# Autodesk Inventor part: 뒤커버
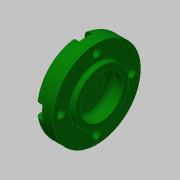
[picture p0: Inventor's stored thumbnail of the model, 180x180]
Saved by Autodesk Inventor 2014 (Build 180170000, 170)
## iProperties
Created: 2015-11
Part Number: 뒤커버
Material: 알루미늄 6061
Document SubType Name: Modeling
Designer: mduedu
Density: 1 g/cm^3
Appearance: 진녹색
Author: mduedu
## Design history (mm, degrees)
sketch "스케치1"
  geometry: L1 (-7, 0)-(7, 0); L2 (-7, 0)-(-7, 26); L3 (-7, 26)-(4, 26); L4 (4, 26)-(4, 16); L5 (4, 16)-(7, 16); L6 (7, 16)-(7, 0); 2 further points
  constraints: 12 end point, 3 perpendicular, 2 parallel, 1 coincident, 1 horizontal, 1 midpoint
  dimensions: "d0" = 14 distance of L1.start L1.end; "d1" = 52 diameter of L3 L1; "d2" = 3 distance of L4.end L5.end; "d3" = 32 diameter of L5 L1
revolve "회전1" sketch "스케치1" stored, may be unused: angle "d4" = 90 deg
hole "구멍1" diameter "d7" = 25; stored, may be unused: countersink angle "d11" = 90 deg, drill point angle "d13" = 0 deg; dims "d8" = 6, "d9" = 4, "d10" = 2, "d12" = 8, "d62" = 10, "d63" = 10
fillet "모깎기2" dims "d36" = 3
fillet "모깎기3" dims "d37" = 3
fillet "모깎기4" dims "d38" = 0.3
sketch "스케치3" dims "d61" = 42
  geometry: C1 r 26 at (0, 0) reference; 2 further points
  constraints: 2 vertical alignment, 1 coincident, 2 other
hole "구멍4" sketch "스케치3" at (0, -21) diameter "d44" = 4.5; stored, may be unused: countersink angle "d48" = 90 deg, drill point angle "d50" = 0 deg; dims "d45" = 6, "d46" = 8, "d47" = 4.6, "d49" = 8
sketch "스케치4"
  geometry: L1 (-4, 0)-(-4, -4.69); L2 (4, 0)-(4, -4.69); A1 r 4 centre (0, 0) between (3.614, -1.714) and (-3.614, -1.714) reference; A2 r 26 centre (0, 21) between (-4, -4.69) and (4, -4.69) reference; 1 further point
  constraints: 4 end point, 4 point on circle, 2 tangent, 1 parallel, 1 vertical
extrude "돌출1" cut sketch "스케치4" stored distance "d51" = 0; taper "d52" = 0 deg
node "솔리드1"
pattern_circular "원형 패턴1" dims angle "d54" = 360 deg
